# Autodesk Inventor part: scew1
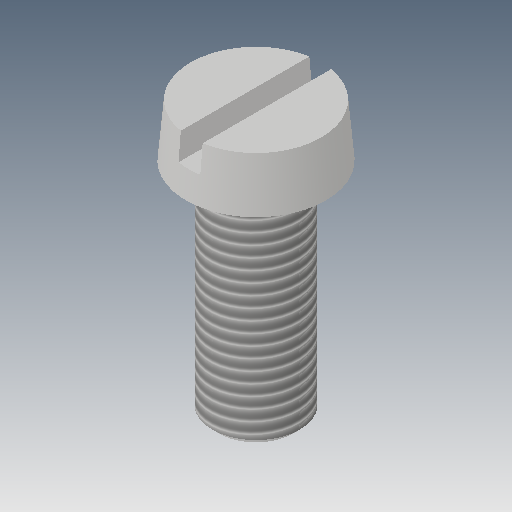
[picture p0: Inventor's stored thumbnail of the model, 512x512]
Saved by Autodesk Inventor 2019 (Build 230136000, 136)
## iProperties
Created: 2016-05
Part Number: scew1
Material: Generic
Document SubType Name: Modeling
Designer: CADCIM
Density: 1 g/cm^3
Appearance: Default
Author: CADCIM
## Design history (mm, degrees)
sketch "Sketch1"
  geometry: C1 r 9.6 at (0, 0); 1 further point
  constraints: 1 centre point, 1 coincident
  dimensions: "d0" = 19.2 diameter of C1
extrude "Extrusion1" new body sketch "Sketch1" distance "d1" = 7.2; taper "d2" = -5 deg
sketch "Sketch3"
  geometry: C1 r 6 at (0, 0); 1 further point
  constraints: 1 centre point, 1 coincident
  dimensions: "d7" = 12 diameter of C1
extrude "Extrusion3" join sketch "Sketch3" distance "d8" = 30; taper "d9" = 0 deg
thread "Thread1" dims "d13" = 10, "d14" = 0
chamfer "Chamfer2" distance "d15" = 0.9; stored, may be unused: second distance "d16" = 2, angle "d17" = 45 deg
sketch "Sketch4"
  geometry: L1 (1.5, -10.35)-(-1.5, -10.35); L2 (-1.5, -10.35)-(-1.5, 10.35); L3 (-1.5, 10.35)-(1.5, 10.35); L4 (1.5, 10.35)-(1.5, -10.35); L5 (0, -10.35)-(0, 10.35); 2 further points
  constraints: 10 end point, 3 midpoint, 2 parallel, 1 coincident, 1 horizontal, 1 perpendicular
  dimensions: "d18" = 3 distance of L1.start L1.end
extrude "Extrusion4" cut sketch "Sketch4" distance "d19" = 3.6; taper "d20" = 0 deg
body "Solid1"
